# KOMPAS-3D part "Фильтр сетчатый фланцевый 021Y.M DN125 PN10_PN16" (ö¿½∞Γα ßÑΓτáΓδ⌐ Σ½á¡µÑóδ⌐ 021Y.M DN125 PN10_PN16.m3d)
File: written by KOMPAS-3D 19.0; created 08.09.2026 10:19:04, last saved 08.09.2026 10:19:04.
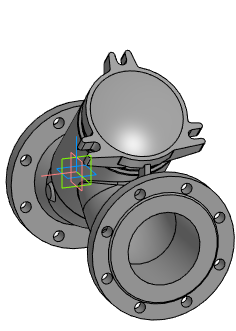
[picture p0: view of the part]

Document properties: Автор: Энергия; Полное имя файла: Z:\3.Личные\sachek\Dendor\_3D для проектировщиков\8.2 Фильтр сетчатый 021Y.M\021Y.M_STP\Фильтр сетчатый фланцевый 021Y.M DN125 PN10_PN16.m3d

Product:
- Part/product: Фильтр сетчатый фланцевый 021Y.M DN125 PN10_PN16

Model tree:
1. Операция без истории:1  (labels: Фильтр сетчатый фланцевый 021Y.M DN125 PN10_PN16)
